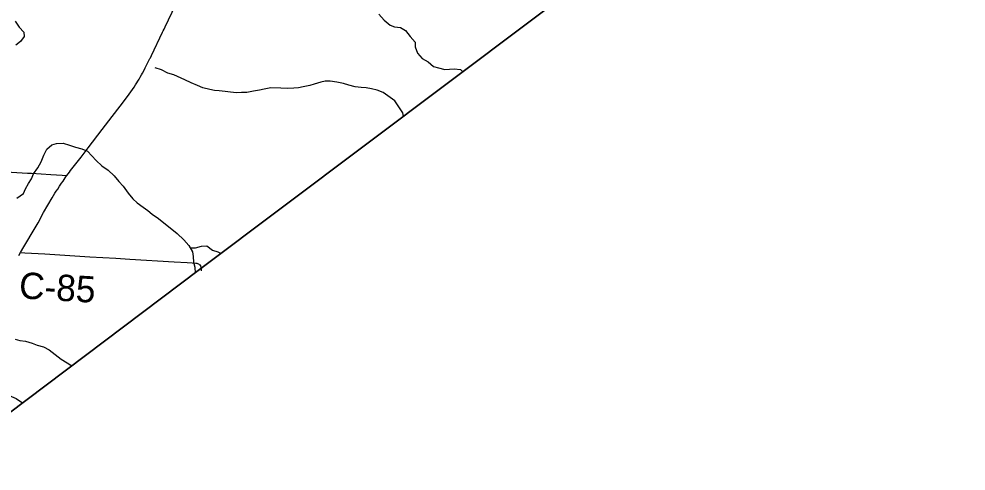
# Model space of a CAD drawing. Extents: x 1442749 to 1756758, y 235267 to 677782.
# Drawn here: x 1606204 to 1616991, y 462917 to 468064 of the extents above; entities that cross this region are included whole.
import ezdxf

# ---------------------------------------------------------------- set-up
doc = ezdxf.new("R2010")
doc.units = 0
for name, color, linetype in [('GM_X_Adjacent_County', 7, 'Continuous'), ('GM_X_County', 7, 'Continuous'), ('GM_X_County_Road', 7, 'Continuous'), ('GM_X_County_Road_Text', 7, 'Continuous'), ('GM_X_Major_River', 7, 'Continuous'), ('GM_X_Minor_River', 7, 'Continuous'), ('GM_X_State_Route', 7, 'Continuous'), ('GM_X_Township', 7, 'Continuous')]:
    doc.layers.add(name, color=color, linetype=linetype)

msp = doc.modelspace()

# ---------------------------------------------------------------- linework, layer by layer
at = {"layer": 'GM_X_Adjacent_County'}
msp.add_lwpolyline([(1605211, 462917), (1608261, 465210), (1612987, 468763), (1614700, 470050), (1618604, 472952)], dxfattribs=at)
at = {"layer": 'GM_X_County'}
msp.add_lwpolyline([(1618604, 472952), (1614700, 470050), (1612987, 468763), (1608261, 465210), (1605211, 462917)], dxfattribs=at)
at = {"layer": 'GM_X_County_Road'}
for points in [[(1604158, 466437), (1604189, 466435), (1604408, 466424), (1604745, 466405), (1605027, 466388), (1605413, 466365), (1605692, 466346), (1606303, 466309), (1606324, 466308), (1606346, 466307), (1606566, 466294), (1606697, 466285), (1606749, 466281)], [(1606221, 465406), (1606269, 465403), (1606498, 465389), (1607012, 465357), (1607307, 465339), (1607468, 465330), (1607972, 465299), (1608120, 465290), (1608175, 465287), (1608217, 465284), (1608228, 465282), (1608237, 465280), (1608249, 465275), (1608257, 465270), (1608264, 465263), (1608270, 465255), (1608273, 465250), (1608275, 465243), (1608277, 465237), (1608278, 465231), (1608279, 465216), (1608278, 465195)]]:
    msp.add_lwpolyline(points, dxfattribs=at)
at = {"layer": 'GM_X_Major_River'}
msp.add_lwpolyline([(1606160, 468037), (1606206, 467970), (1606261, 467915), (1606262, 467865), (1606223, 467807), (1606168, 467764)], dxfattribs=at)
at = {"layer": 'GM_X_Minor_River'}
for points in [[(1610303, 468118), (1610362, 468051), (1610432, 467992), (1610483, 467973), (1610548, 467967), (1610605, 467934), (1610660, 467863), (1610718, 467798), (1610717, 467746), (1610742, 467675), (1610795, 467613), (1610863, 467576), (1610925, 467523), (1610981, 467508), (1611055, 467489), (1611107, 467494), (1611159, 467498), (1611231, 467487), (1611259, 467462)], [(1610585, 466955), (1610575, 466996), (1610531, 467065), (1610484, 467130), (1610431, 467170), (1610353, 467227), (1610285, 467252), (1610221, 467269), (1610157, 467278), (1610101, 467285), (1610033, 467292), (1609961, 467309), (1609899, 467328), (1609825, 467345), (1609747, 467356), (1609693, 467354), (1609641, 467343), (1609568, 467322), (1609516, 467308), (1609439, 467291), (1609389, 467280), (1609333, 467275), (1609261, 467272), (1609187, 467277), (1609074, 467278), (1608998, 467263), (1608942, 467252), (1608875, 467243), (1608801, 467228), (1608739, 467226), (1608680, 467223), (1608612, 467230), (1608554, 467239), (1608486, 467244), (1608430, 467248), (1608376, 467259), (1608300, 467278), (1608236, 467307), (1608167, 467338), (1608095, 467371), (1607969, 467427), (1607901, 467448), (1607828, 467485), (1607754, 467506)], [(1606179, 466023), (1606254, 466076), (1606279, 466130), (1606312, 466189), (1606347, 466245), (1606370, 466299), (1606417, 466370), (1606456, 466438), (1606487, 466512), (1606520, 466580), (1606579, 466631), (1606631, 466648), (1606707, 466649), (1606779, 466628), (1606849, 466605), (1606919, 466586), (1606983, 466560), (1607034, 466505), (1607082, 466452), (1607149, 466391), (1607219, 466344), (1607290, 466279), (1607343, 466212), (1607391, 466161), (1607446, 466080), (1607499, 466016), (1607551, 465971), (1607618, 465922), (1607670, 465885), (1607721, 465840), (1607793, 465791), (1608007, 465620), (1608080, 465549), (1608140, 465484), (1608181, 465414), (1608188, 465361), (1608193, 465297), (1608206, 465237), (1608211, 465171)], [(1608156, 465457), (1608213, 465459), (1608282, 465478), (1608342, 465482), (1608408, 465431), (1608468, 465412), (1608506, 465392)], [(1606160, 464419), (1606214, 464403), (1606278, 464394), (1606354, 464373), (1606410, 464350), (1606482, 464333), (1606549, 464298), (1606617, 464245), (1606686, 464192), (1606752, 464149), (1606807, 464115)], [(1604793, 463766), (1604845, 463761), (1604916, 463756), (1604984, 463749), (1605038, 463734), (1605090, 463724), (1605162, 463711), (1605230, 463694), (1605282, 463681), (1605340, 463668), (1605460, 463655), (1605516, 463650), (1605566, 463649), (1605620, 463655), (1605682, 463662), (1605757, 463673), (1605815, 463686), (1605882, 463722), (1605955, 463771), (1606031, 463780), (1606093, 463779), (1606171, 463742), (1606246, 463694)]]:
    msp.add_lwpolyline(points, dxfattribs=at)
at = {"layer": 'GM_X_State_Route'}
msp.add_lwpolyline([(1606201, 465371), (1606221, 465406), (1606259, 465470), (1606388, 465686), (1606421, 465743), (1606485, 465861), (1606582, 466029), (1606598, 466054), (1606613, 466080), (1606628, 466102), (1606645, 466127), (1606667, 466161), (1606689, 466193), (1606706, 466219), (1606730, 466254), (1606747, 466278), (1606749, 466281), (1606763, 466299), (1606779, 466321), (1606792, 466339), (1606911, 466492), (1606994, 466597), (1607150, 466804), (1607228, 466906), (1607395, 467121), (1607459, 467208), (1607516, 467288), (1607533, 467315), (1607546, 467335), (1607559, 467355), (1607572, 467377), (1607586, 467402), (1607601, 467428), (1607611, 467446), (1607626, 467475), (1607642, 467506), (1607696, 467612), (1607701, 467623), (1607714, 467649), (1607839, 467912), (1607847, 467928), (1607856, 467948), (1607870, 467976), (1607985, 468222)], dxfattribs=at)
at = {"layer": 'GM_X_Township'}
msp.add_lwpolyline([(1618604, 472952), (1614700, 470050), (1612987, 468763), (1608261, 465210), (1605211, 462917)], dxfattribs=at)

# ---------------------------------------------------------------- texts
at = {"layer": 'GM_X_County_Road_Text'}
msp.add_text('C-85', height=300, rotation=356.5725, dxfattribs=at).set_placement((1606199, 464884))

doc.saveas('drawing.dxf')
